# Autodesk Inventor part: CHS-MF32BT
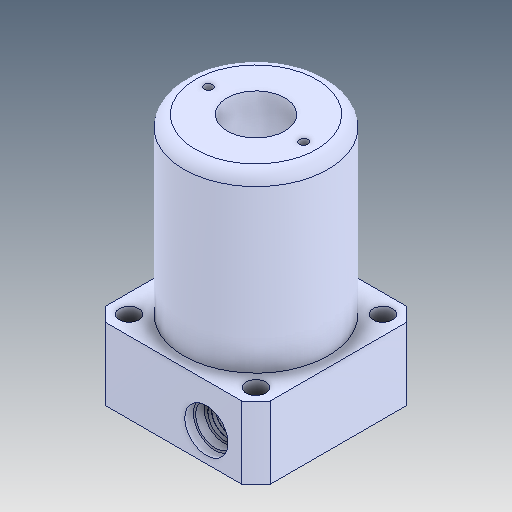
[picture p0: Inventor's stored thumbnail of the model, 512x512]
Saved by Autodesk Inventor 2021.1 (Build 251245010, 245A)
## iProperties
Created: 2021-05
Part Number: CHS-MF32BT
Material: Ogólny
Document SubType Name: Modeling
Designer: user
Density: 1 g/cm^3
Appearance: Domyślna
Author: user
Revision Number: ÈÎºÎ
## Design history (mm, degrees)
feature "Í¹Ì¨-À­Éì1"
node "Bryła1"
